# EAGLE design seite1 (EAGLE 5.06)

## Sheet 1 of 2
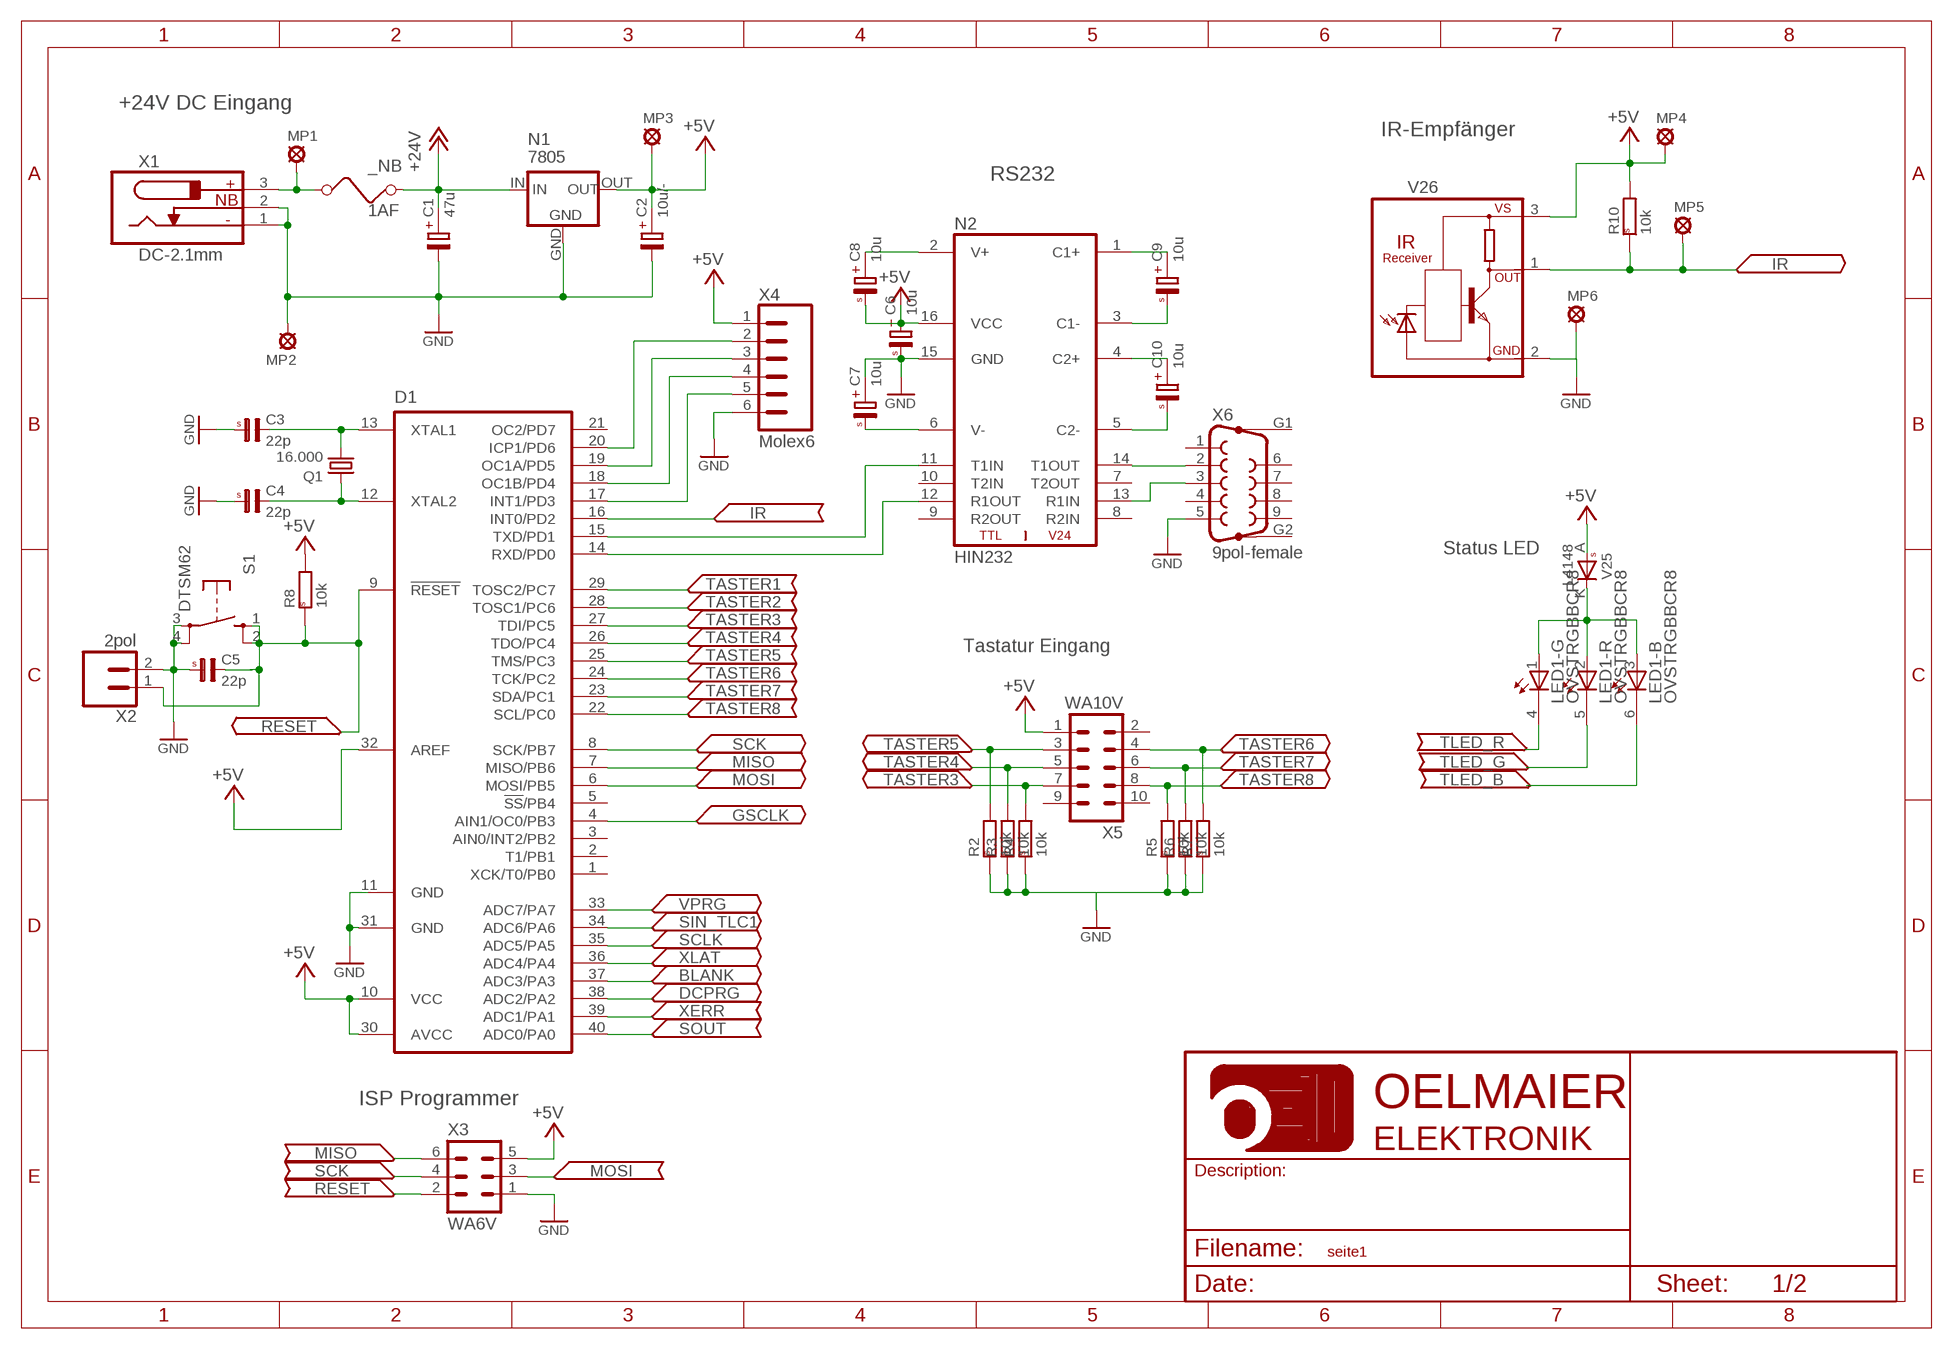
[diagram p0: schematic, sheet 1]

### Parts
_NB  1AF  FUSE5X20  [FUSE5X20]
C1  47u  E2,5-6  [E2,5-6]
C2  10u/-  E2,5-5  [E2,5-5]
C3  22p  C0805W  [C0805#W]
C4  22p  C0805W  [C0805#W]
C5  22p  C0805W  [C0805#W]
C6  10u  CE-B4  [CE-B4]
C7  10u  CE-B4  [CE-B4]
C8  10u  CE-B4  [CE-B4]
C9  10u  CE-B4  [CE-B4]
C10  10u  CE-B4  [CE-B4]
D1  ATMEGA16  [DIL40]
F1_H  FUSE_C1  [FUSE_C1]
LED1  OVSTRGBBCR8  [OVSTRGBBCR8]
MP1  LN13  [LN13]
MP2  LN13  [LN13]
MP3  LN13  [LN13]
MP4  LN13  [LN13]
MP5  LN13  [LN13]
MP6  LN13  [LN13]
N1  7805  78XXD2PAC  [D2PACVR]
N2  HIN232  MAX232-L  [SO16W#R]
Q1  16.000  Q_HC49P  [Q_HC49P]
R2  10k  R0603R1  [R06031#R]
R3  10k  R0603R1  [R06031#R]
R4  10k  R0603R1  [R06031#R]
R5  10k  R0603R1  [R06031#R]
R6  10k  R0603R1  [R06031#R]
R7  10k  R0603R1  [R06031#R]
R8  10k  R0603R1  [R06031#R]
R10  10k  R1206W1  [R12061#W]
S1  DTSM62  [DTSM62]
V25  L4148  DIODE-MLL34R  [MLL34#R]
V26  TSOP4836  [TSOP48]
X1  DC-2.1mm  DS-025B  [DS-025B]
X2  2pol  C254_02_SLV  [1X02]
X3  WA6V  WA06V  [WA06V]
X4  Molex6  C254_06_6410  [M6410_06]
X5  WA10V  [WA10V]
X6  9pol-female  F09HP  [F09HP]

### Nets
+5V: C2.+ C6.+ C8.- D1.10(VCC) D1.30(AVCC) D1.32(AREF) MP3.MP MP4.MP N1.OUT N2.16(VCC) R8.2 R10.2 V25.A V26.3(VS) X3.5 X4.1 X5.1 ; also sheet 2
+24V: C1.+ F1_H.2 F1_H.2A N1.IN ; also sheet 2
BLANK: D1.37(ADC3/PA3) ; also sheet 2
DCPRG: D1.38(ADC2/PA2) ; also sheet 2
F3: F1_H.1 F1_H.1A MP1.MP X1.3(+)
GND: C1.- C2.- C3.1 C4.1 C5.1 C6.- C7.+ D1.31(GND) MP2.MP MP6.MP N1.GND N2.15(GND) R2.1 R3.1 R4.1 R5.1 R6.1 R7.1 S1.3 S1.4 V26.2(GND) X1.1(-) X1.2(NB) X2.2 X3.1 X4.6 X6.5 ; also sheet 2
GSCLK: D1.4(AIN1/OC0/PB3) ; also sheet 2
IR: D1.16(INT0/PD2) MP5.MP R10.1 V26.1(OUT)
MISO: D1.7(MISO/PB6) X3.6
MOSI: D1.6(MOSI/PB5) X3.3
N$1: C3.2 D1.13(XTAL1) Q1.2
N$2: C4.2 D1.12(XTAL2) Q1.1
N$27: D1.20(ICP1/PD6) X4.2
N$28: D1.19(OC1A/PD5) X4.3
N$29: LED1.1(-G:A) LED1.3(-B:A) V25.K
N$30: D1.18(OC1B/PD4) X4.4
N$31: D1.17(INT1/PD3) X4.5
N$33: N2.14(T1OUT) X6.2
N$34: N2.13(R1IN) X6.3
N$35: C8.+ N2.2(V+)
N$38: C7.- N2.6(V-)
N$39: C9.+ N2.1(C1+)
N$40: C9.- N2.3(C1-)
N$41: C10.+ N2.4(C2+)
N$42: C10.- N2.5(C2-)
RESET: C5.2 D1.9(!RESET) R8.1 S1.1 S1.2 X2.1 X3.2
RXD: D1.14(RXD/PD0) N2.12(R1OUT)
SCK: D1.8(SCK/PB7) X3.4
SCLK: D1.35(ADC5/PA5) ; also sheet 2
SIN_TLC1: D1.34(ADC6/PA6) ; also sheet 2
SOUT: D1.40(ADC0/PA0) ; also sheet 2
TASTER1: D1.29(TOSC2/PC7)
TASTER2: D1.28(TOSC1/PC6)
TASTER3: D1.27(TDI/PC5) R4.2 X5.7
TASTER4: D1.26(TDO/PC4) R3.2 X5.5
TASTER5: D1.25(TMS/PC3) R2.2 X5.3
TASTER6: D1.24(TCK/PC2) R7.2 X5.4
TASTER7: D1.23(SDA/PC1) R6.2 X5.6
TASTER8: D1.22(SCL/PC0) R5.2 X5.8
TLED_B: LED1.6(-B:C) ; also sheet 2
TLED_G: LED1.5(-R:C) ; also sheet 2
TLED_R: LED1.4(-G:C) ; also sheet 2
TXD: D1.15(TXD/PD1) N2.11(T1IN)
VPRG: D1.33(ADC7/PA7) ; also sheet 2
XERR: D1.39(ADC1/PA1) ; also sheet 2
XLAT: D1.36(ADC4/PA4) ; also sheet 2
Unconnected: D1.1(XCK/T0/PB0) D1.2(T1/PB1) D1.3(AIN0/INT2/PB2) D1.5(!SS!/PB4) D1.11(GND) D1.21(OC2/PD7) LED1.2(-R:A) LED1.4@1(-G:C) LED1.5@1(-R:C) LED1.6@1(-B:C) N2.7(T2OUT) N2.8(R2IN) N2.9(R2OUT) N2.10(T2IN) X5.2 X5.9 X5.10 X6.1 X6.4 X6.6 X6.7 X6.8 X6.9 X6.G1 X6.G2

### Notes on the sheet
- +24V DC Eingang
- IR-Empfänger
- RS232
- Status LED
- Tastatur Eingang
- ISP Programmer

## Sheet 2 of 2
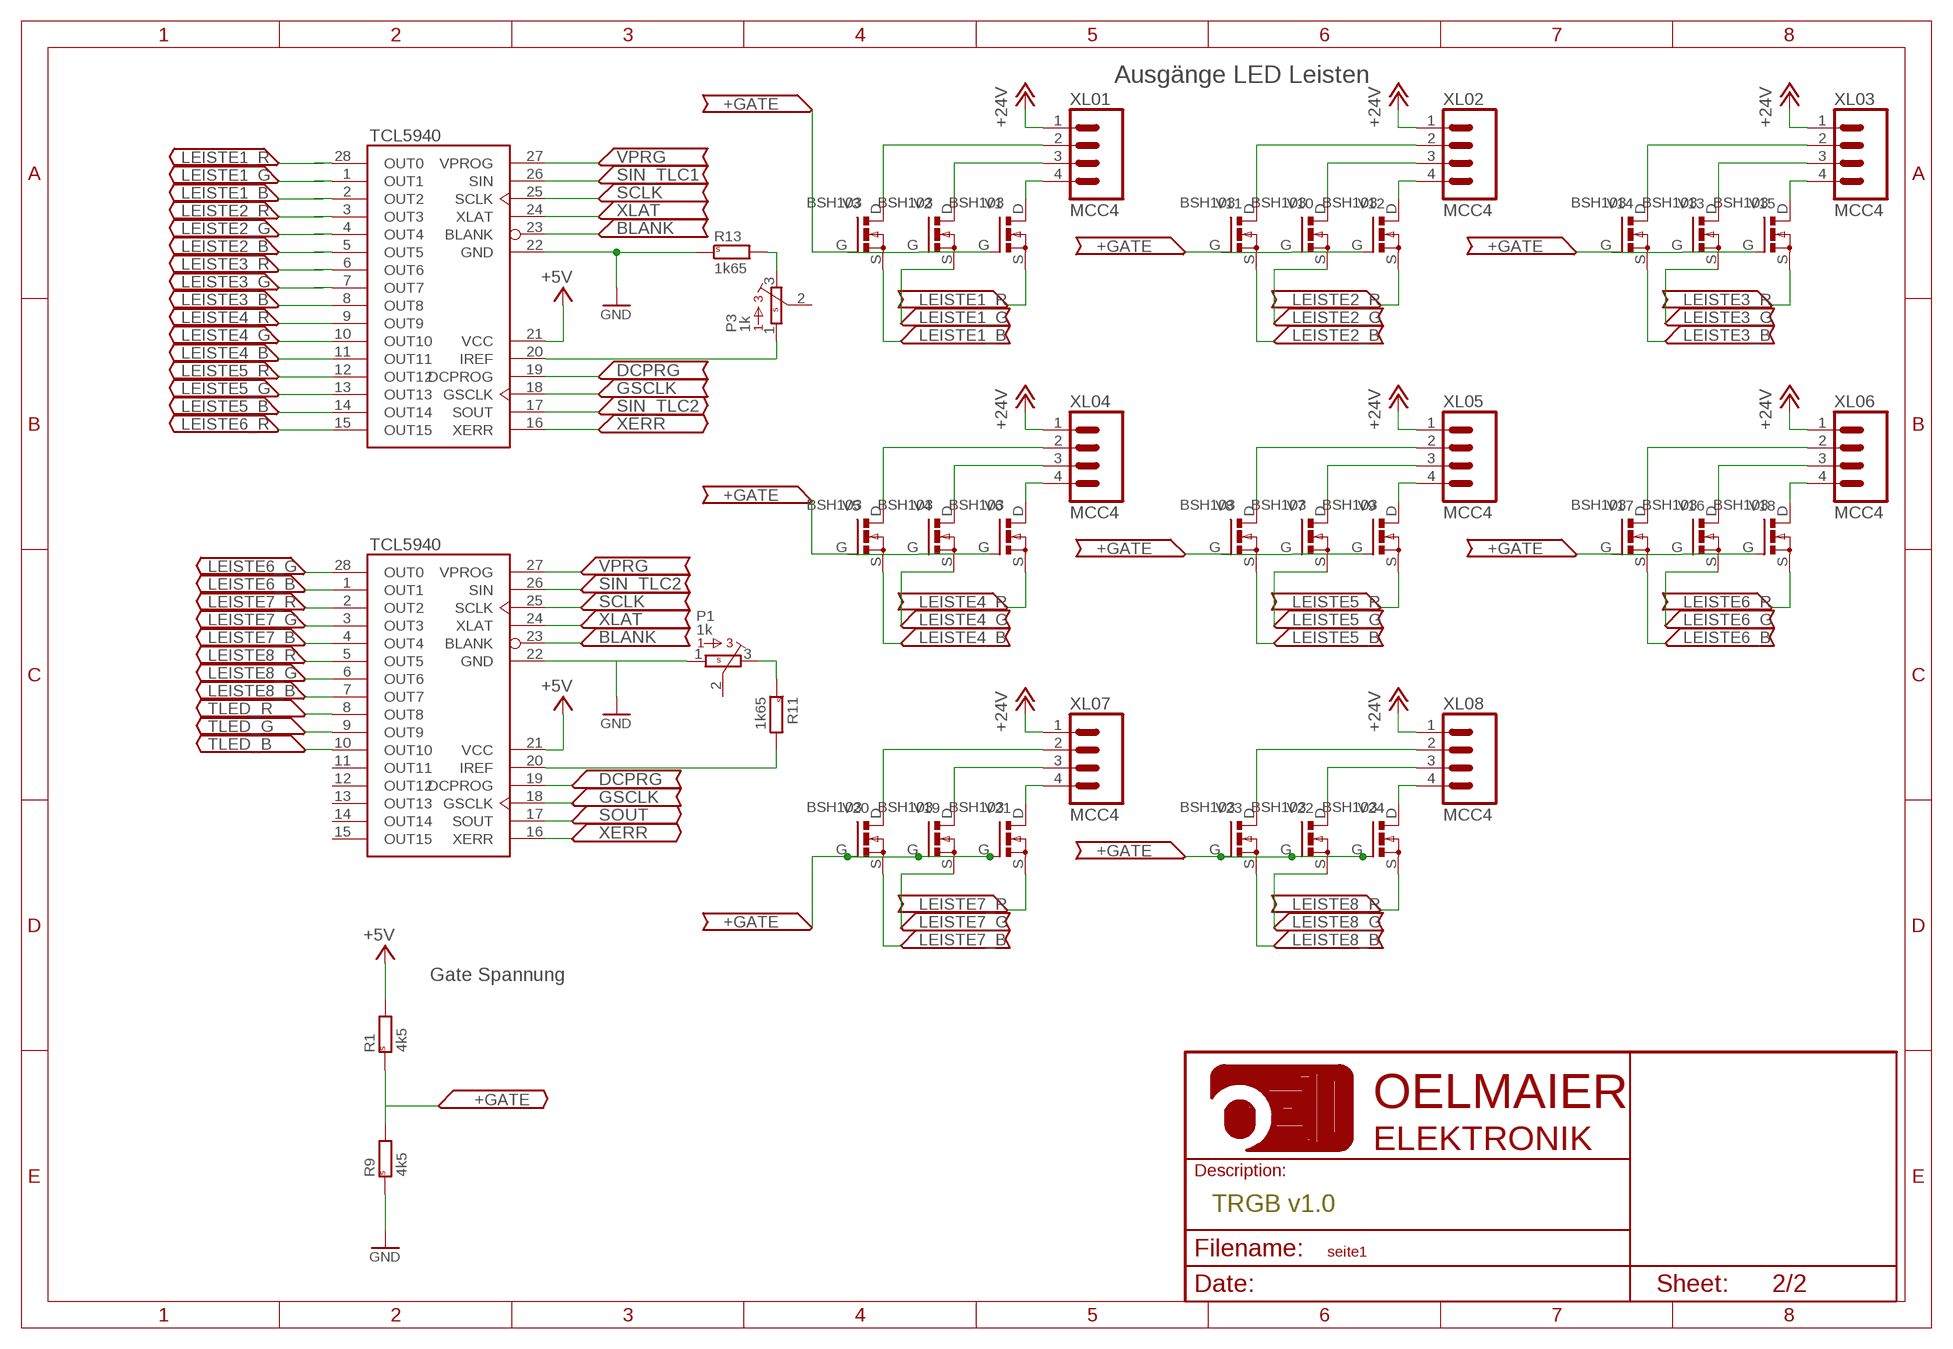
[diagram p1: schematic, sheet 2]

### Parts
IC1  TCL5940  [DIP28]
IC2  TCL5940  [DIP28]
P1  1k  TR-BI23B  [TR-BI23B]
P3  1k  TR-BI23B  [TR-BI23B]
R1  4k5  R1206W1  [R12061#W]
R9  4k5  R1206W1  [R12061#W]
R11  1k65  R1206W1  [R12061#W]
R13  1k65  R1206W1  [R12061#W]
V1  BSH103  MFET-SR  [SOT-23M#R]
V2  BSH103  MFET-SR  [SOT-23M#R]
V3  BSH103  MFET-SR  [SOT-23M#R]
V4  BSH103  MFET-SR  [SOT-23M#R]
V5  BSH103  MFET-SR  [SOT-23M#R]
V6  BSH103  MFET-SR  [SOT-23M#R]
V7  BSH103  MFET-SR  [SOT-23M#R]
V8  BSH103  MFET-SR  [SOT-23M#R]
V9  BSH103  MFET-SR  [SOT-23M#R]
V10  BSH103  MFET-SR  [SOT-23M#R]
V11  BSH103  MFET-SR  [SOT-23M#R]
V12  BSH103  MFET-SR  [SOT-23M#R]
V13  BSH103  MFET-SR  [SOT-23M#R]
V14  BSH103  MFET-SR  [SOT-23M#R]
V15  BSH103  MFET-SR  [SOT-23M#R]
V16  BSH103  MFET-SR  [SOT-23M#R]
V17  BSH103  MFET-SR  [SOT-23M#R]
V18  BSH103  MFET-SR  [SOT-23M#R]
V19  BSH103  MFET-SR  [SOT-23M#R]
V20  BSH103  MFET-SR  [SOT-23M#R]
V21  BSH103  MFET-SR  [SOT-23M#R]
V22  BSH103  MFET-SR  [SOT-23M#R]
V23  BSH103  MFET-SR  [SOT-23M#R]
V24  BSH103  MFET-SR  [SOT-23M#R]
XL01  MCC4  C381_04H  [AL381_04]
XL02  MCC4  C381_04H  [AL381_04]
XL03  MCC4  C381_04H  [AL381_04]
XL04  MCC4  C381_04H  [AL381_04]
XL05  MCC4  C381_04H  [AL381_04]
XL06  MCC4  C381_04H  [AL381_04]
XL07  MCC4  C381_04H  [AL381_04]
XL08  MCC4  C381_04H  [AL381_04]

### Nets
+5V: IC1.21(VCC) IC2.21(VCC) R1.2 ; also sheet 1
+24V: XL01.1 XL02.1 XL03.1 XL04.1 XL05.1 XL06.1 XL07.1 XL08.1 ; also sheet 1
+GATE: R1.1 R9.2 V1.G V2.G V3.G V4.G V5.G V6.G V7.G V8.G V9.G V10.G V11.G V12.G V13.G V14.G V15.G V16.G V17.G V18.G V19.G V20.G V21.G V22.G V23.G V24.G
BLANK: IC1.23(BLANK) IC2.23(BLANK) ; also sheet 1
DCPRG: IC1.19(DCPROG) IC2.19(DCPROG) ; also sheet 1
GND: IC1.22(GND) IC2.22(GND) P1.1 R9.1 R13.1 ; also sheet 1
GSCLK: IC1.18(GSCLK) IC2.18(GSCLK) ; also sheet 1
LEISTE1_B: IC1.2(OUT2) V3.S
LEISTE1_G: IC1.1(OUT1) V2.S
LEISTE1_R: IC1.28(OUT0) V1.S
LEISTE2_B: IC1.5(OUT5) V11.S
LEISTE2_G: IC1.4(OUT4) V10.S
LEISTE2_R: IC1.3(OUT3) V12.S
LEISTE3_B: IC1.8(OUT8) V14.S
LEISTE3_G: IC1.7(OUT7) V13.S
LEISTE3_R: IC1.6(OUT6) V15.S
LEISTE4_B: IC1.11(OUT11) V5.S
LEISTE4_G: IC1.10(OUT10) V4.S
LEISTE4_R: IC1.9(OUT9) V6.S
LEISTE5_B: IC1.14(OUT14) V8.S
LEISTE5_G: IC1.13(OUT13) V7.S
LEISTE5_R: IC1.12(OUT12) V9.S
LEISTE6_B: IC2.1(OUT1) V17.S
LEISTE6_G: IC2.28(OUT0) V16.S
LEISTE6_R: IC1.15(OUT15) V18.S
LEISTE7_B: IC2.4(OUT4) V20.S
LEISTE7_G: IC2.3(OUT3) V19.S
LEISTE7_R: IC2.2(OUT2) V21.S
LEISTE8_B: IC2.7(OUT7) V23.S
LEISTE8_G: IC2.6(OUT6) V22.S
LEISTE8_R: IC2.5(OUT5) V24.S
N$3: V1.D XL01.4
N$4: V2.D XL01.3
N$5: V3.D XL01.2
N$6: V12.D XL02.4
N$7: V10.D XL02.3
N$8: V11.D XL02.2
N$9: V15.D XL03.4
N$10: V13.D XL03.3
N$11: V14.D XL03.2
N$12: V6.D XL04.4
N$13: V4.D XL04.3
N$14: V5.D XL04.2
N$15: V9.D XL05.4
N$16: V7.D XL05.3
N$17: V8.D XL05.2
N$18: V18.D XL06.4
N$19: V16.D XL06.3
N$20: V17.D XL06.2
N$21: V21.D XL07.4
N$22: V19.D XL07.3
N$23: V20.D XL07.2
N$24: V24.D XL08.4
N$25: V22.D XL08.3
N$26: V23.D XL08.2
N$32: IC2.20(IREF) R11.2
N$36: P1.3 R11.1
N$37: IC1.20(IREF) P3.1
N$43: P3.3 R13.2
SCLK: IC1.25(SCLK) IC2.25(SCLK) ; also sheet 1
SIN_TLC1: IC1.26(SIN) ; also sheet 1
SIN_TLC2: IC1.17(SOUT) IC2.26(SIN)
SOUT: IC2.17(SOUT) ; also sheet 1
TLED_B: IC2.10(OUT10) ; also sheet 1
TLED_G: IC2.9(OUT9) ; also sheet 1
TLED_R: IC2.8(OUT8) ; also sheet 1
VPRG: IC1.27(VPROG) IC2.27(VPROG) ; also sheet 1
XERR: IC1.16(XERR) IC2.16(XERR) ; also sheet 1
XLAT: IC1.24(XLAT) IC2.24(XLAT) ; also sheet 1
Unconnected: IC2.11(OUT11) IC2.12(OUT12) IC2.13(OUT13) IC2.14(OUT14) IC2.15(OUT15) P1.2 P3.2

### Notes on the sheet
- Ausgänge LED Leisten
- Gate Spannung
- TRGB v1.0

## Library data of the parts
_NB = 6ICsocket:FUSE5X20: Feinsicherung 5 x 20mm
C1 C2 = 4CE:E2,5: Elko radial RM 2,5 mm
C3-C5 = 8SMDPAS:C: SMD Keramik Chip Kondensator
C6-C10 = 8SMDCE:CE-: SMD Chip Elko auf Kunststoffsockel
D1 = 2MCU:ATMEGA16: 8-bit AVR Microcontroller with 16K Bytes In-System Programmable Flash
F1_H = 6ICsocket:FUSE_C1: Sicherungsclipse 1Paar
IC1 IC2 = tcl5940:TCL5940: 16-Channel 12-Bit LED Driver
LED1 = led:OVSTRGBBCR8: Full Color PLCC6 LED OVSTRGBBCR8 Source: www.optekinc.com .. ovstrgbbcr8.pdf
MP1-MP6 = 6zCon-rib:LN13: Lötstützpunkt mit Öse (1.3mm Bohrung)
N1 = 7LINEAR:78XX: Festspannungsregler DPAK - D2PAK typ. 0.5 - 1A
N2 = 7LINEAR:MAX232-: RS232 TRANSEIVER
P1 P3 = 8SMDEMEC:TR-BI23B: SMD-Trimmer Beckmann BI23
Q1 = 8SMDPAS:Q_HC49P: SMD Quarz
R1-R11 R13 = 8SMDPAS:R: SMD Widerstand
S1 = 8SMDEMEC:DTSM62: SMD-Leiterplattentaster 6x6mm 1,6N Schaltspannung , max. : 12V DC Schaltstrom , max. : 50mA Lebensdauer : 1 Mio. Betätigungen Schaltart : schliesssend Betätigungskraft : 1,6N Betätigungsweg : 0,25mm
V1-V24 = 7SMDDIS:MFET-: N-Kanal MOSFET diverse Gehäuse
V25 = 7SMDDIS:DIODE-: Diode unipolar diverse Packages
V26 = 2OPTO:TSOP48*: IR Receiver Module for infrared remote control systems DeviceCarrier Frequency TSOP483030 kHz TSOP483333 kHz TSOP483636 kHz TSOP483736.7 kHz TSOP483838 kHz TSOP484040 kHz TSOP485656 kHz
X1 = 5CONSUBD:DS-025*: Klinkenbuchse DS-025-A : Mittelkontakt = 2.5 mm DS-025-AS : Mittelkontakt = 2.5 mm mit Schlitz DS-025-B : Mittelkontakt = 2.1 mm DS-025-BS : Mittelkontakt = 2.1 mm mit Schlitz
X2 = 5CON254H:C254_02: 2pol Stiftleiste einreihig RM2.54
X3 = 5CON254F:WA06: 6pol Wannenstiftleiste RM2.54
X4 = 5CON254H:C254_06: 6pol Stiftleiste einreihig RM2.54
X5 = 5CON254F:WA10: 10pol Wannenstiftleiste RM2.54
X6 = 5CONSUBD:F09HP
XL01-XL08 = 5CON381:C381_04: 4pol. Mini-Combicon RM3.81 Nenndaten : max. 160V / 8A Querschnitte max. : 1mm² flexibel / 1,5mm² starr

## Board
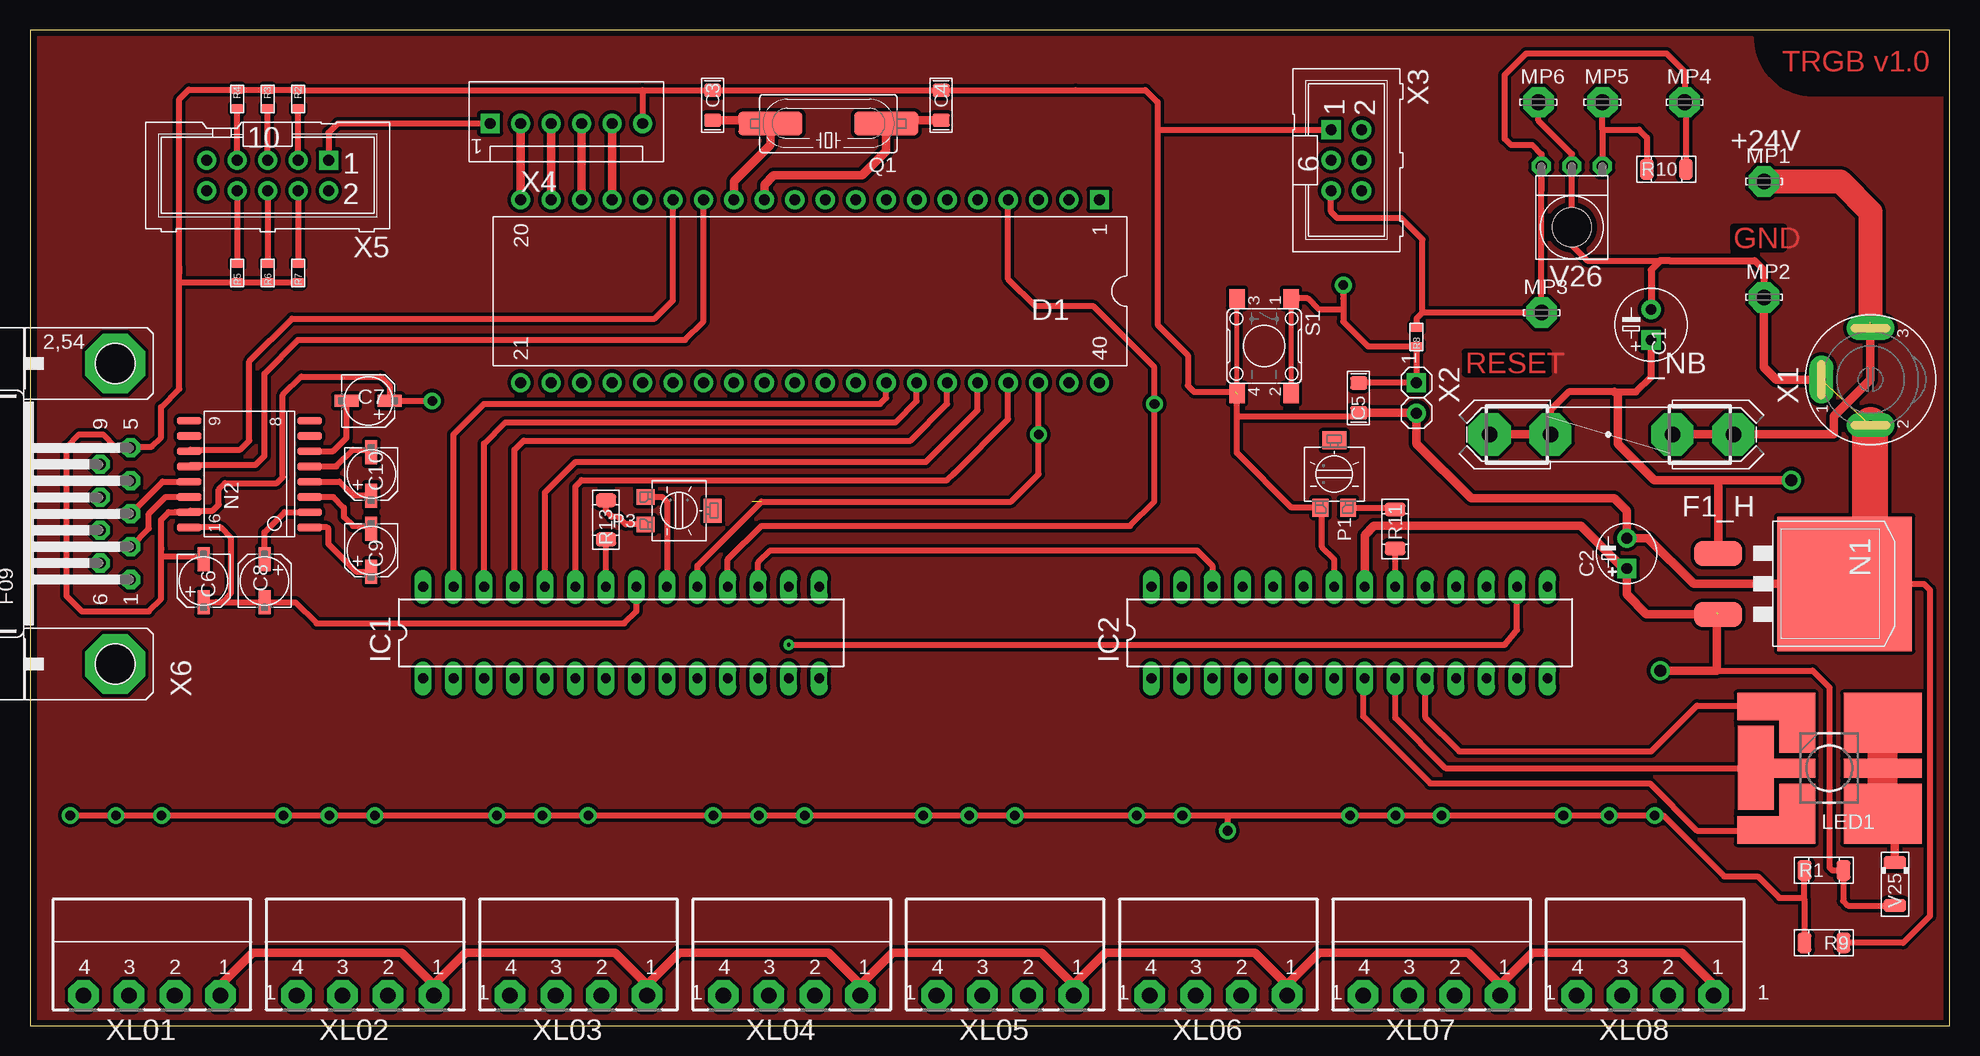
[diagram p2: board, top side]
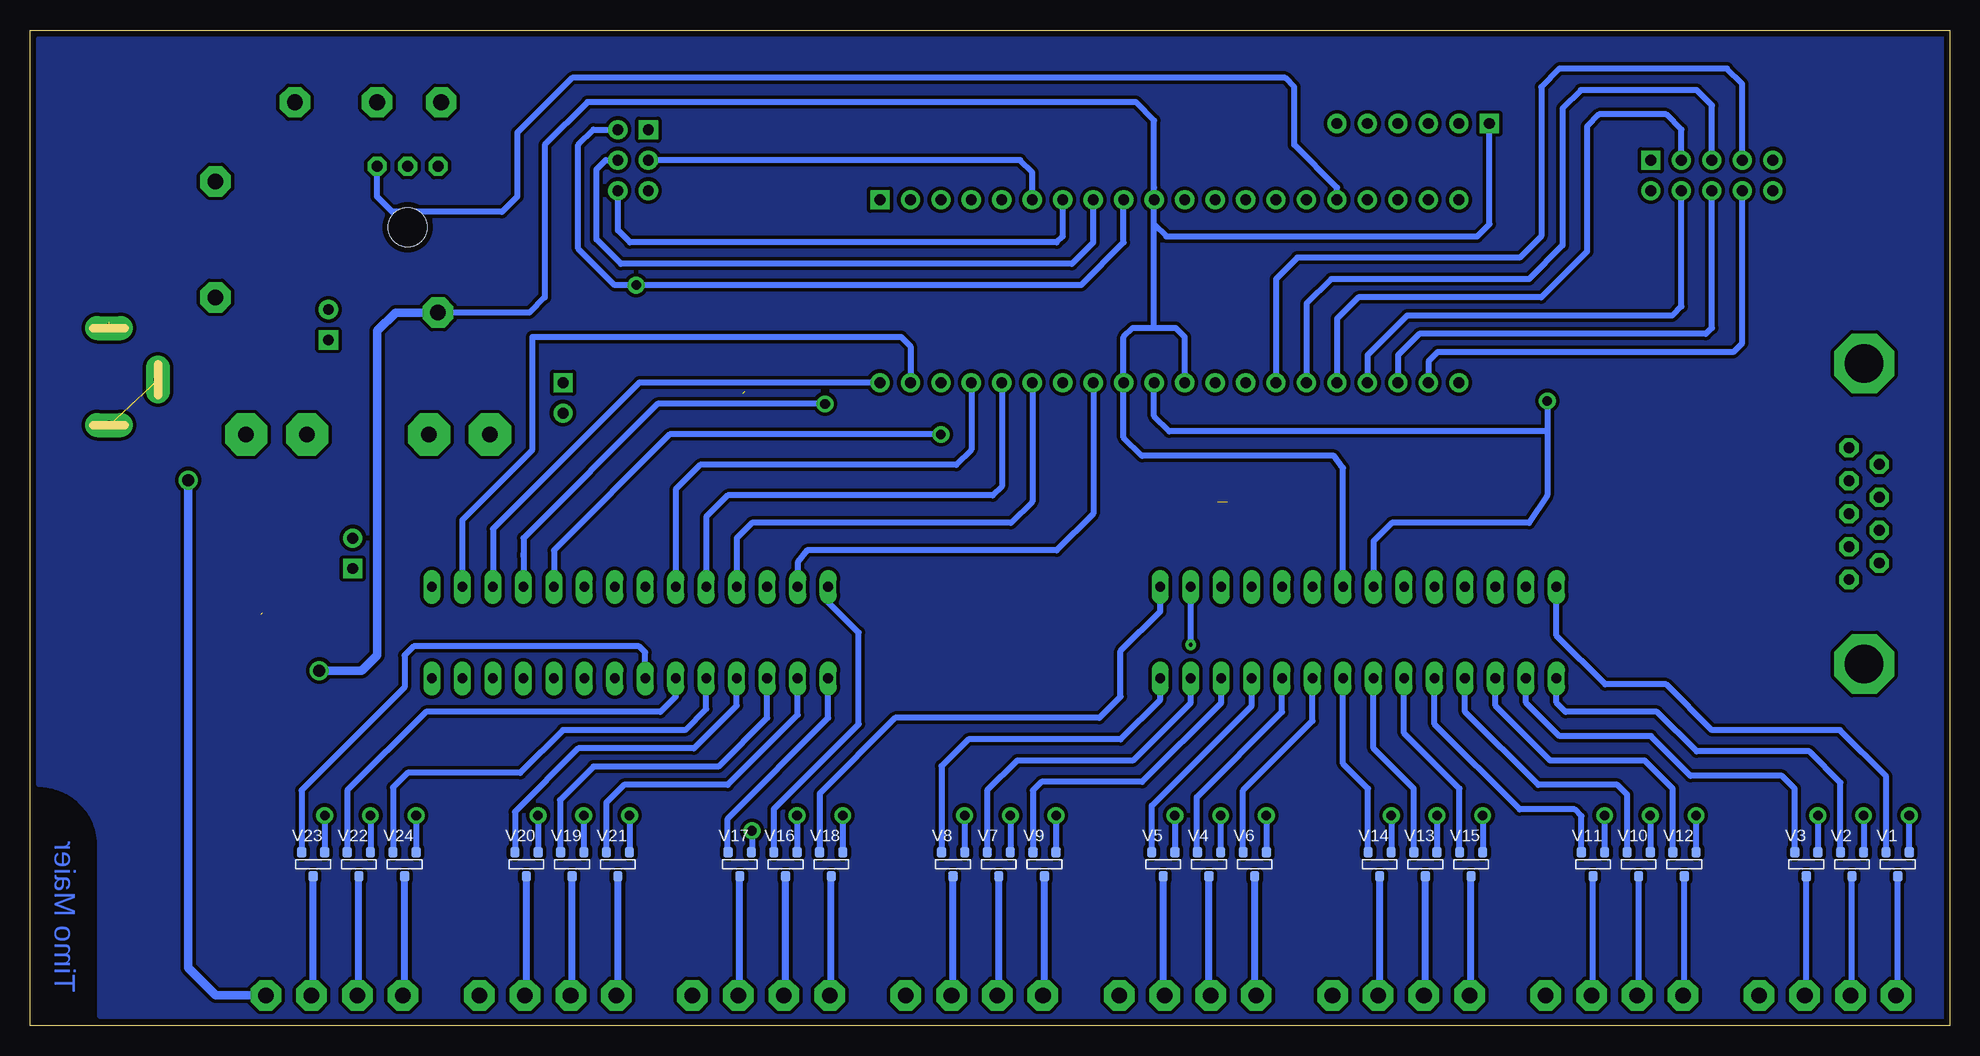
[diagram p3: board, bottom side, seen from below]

Size 160 x 82.98 mm. Coordinates in mm from the lower left corner, seen from the top.
Outline: 0,0 160,0 160,82.98 0,82.98 0,0
Copper layers (1*2*15*16): Top 0.07mm / dielectric 1.5mm / Route2 0.035mm / dielectric 1.5mm / Route15 0.035mm / dielectric 1.5mm / Bottom 0.07mm
Design rules "70um": minimum track width 0.3mm, minimum drill 0.3mm, track to track 0.3mm, track to pad 0.3mm, pad to pad 0.3mm, via to via 0.3mm, smd to smd 0.3mm, copper to edge 0.5mm, drill to drill 0.5mm, minimum pad ring 0.3mm, minimum via ring 0.3mm, stop-mask expansion 0mil, vias tented up to drill 0.6mm, thermal gap 0.3mm

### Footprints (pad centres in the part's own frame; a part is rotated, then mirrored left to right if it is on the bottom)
E2,5-6 = drill 0.9 pad 1.6 square: + -1.27,0 | drill 0.9 pad 1.6 round: - 1.27,0
E2,5-5 = drill 0.9 pad 1.6 square: + -1.27,0 | drill 0.9 pad 1.6 round: - 1.27,0
C0805#W = smd 1.092 x 1.397: 1 -1.245,0; 2 1.245,0
CE-B4 = smd 2 x 1: + -1.8,0; - 1.8,0
DIL40 = drill 0.9 pad 1.6 square: 1 -24.13,-7.62 | drill 0.9 pad 1.6 round: 2 -21.59,-7.62; 3 -19.05,-7.62; 4 -16.51,-7.62; 5 -13.97,-7.62; 6 -11.43,-7.62; 7 -8.89,-7.62; 8 -6.35,-7.62; 9 -3.81,-7.62; 10 -1.27,-7.62; 11 1.27,-7.62; 12 3.81,-7.62; 13 6.35,-7.62; 14 8.89,-7.62; 15 11.43,-7.62; 16 13.97,-7.62; 17 16.51,-7.62; 18 19.05,-7.62; 19 21.59,-7.62; 20 24.13,-7.62; 21 24.13,7.62; 22 21.59,7.62; 23 19.05,7.62; 24 16.51,7.62; 25 13.97,7.62; 26 11.43,7.62; 27 8.89,7.62; 28 6.35,7.62; 29 3.81,7.62; 30 1.27,7.62; 31 -1.27,7.62; 32 -3.81,7.62; 33 -6.35,7.62; 34 -8.89,7.62; 35 -11.43,7.62; 36 -13.97,7.62; 37 -16.51,7.62; 38 -19.05,7.62; 39 -21.59,7.62; 40 -24.13,7.62
FUSE_C1 = drill 1.3 pad 3.505 octagon: 1 -10.16,0; 1A -5.08,0; 2 10.16,0; 2A 5.08,0
DIP28 = drill 0.813 long: 1 -15.24,-3.81; 2 -12.7,-3.81; 3 -10.16,-3.81; 4 -7.62,-3.81; 5 -5.08,-3.81; 6 -2.54,-3.81; 7 0,-3.81; 8 2.54,-3.81; 9 5.08,-3.81; 10 7.62,-3.81; 11 10.16,-3.81; 12 12.7,-3.81; 13 15.24,-3.81; 14 17.78,-3.81; 15 17.78,3.81; 16 15.24,3.81; 17 12.7,3.81; 18 10.16,3.81; 19 7.62,3.81; 20 5.08,3.81; 21 2.54,3.81; 22 0,3.81; 23 -2.54,3.81; 24 -5.08,3.81; 25 -7.62,3.81; 26 -10.16,3.81; 27 -12.7,3.81; 28 -15.24,3.81
OVSTRGBBCR8 = smd 6.5 x 5: 1 -4.442,3.786; 3 -4.442,-3.786 | smd 6.5 x 1.6: 2 -4.442,0 | smd 3 x 5: 4 2.692,3.786; 6 2.692,-3.786 | smd 6.5 x 2.3: 4@1 4.442,5.136; 6@1 4.442,-5.136 | smd 5 x 1.6: 5 3.692,0 | smd 3 x 7: 5@1 6.15,-0.025
LN13 = drill 1.3 pad 2.54 octagon: MP 0,0
D2PACVR = smd 11.2 x 11.2: GND 0,3.175 | smd 2.08 x 4: IN -2.54,-7.366; OUT 2.54,-7.366
SO16W#R = smd 0.66 x 2.032: 1 -4.445,-5.029; 2 -3.175,-5.029; 3 -1.905,-5.029; 4 -0.635,-5.029; 5 0.635,-5.029; 6 1.905,-5.029; 7 3.175,-5.029; 8 4.445,-5.029; 9 4.445,5.029; 10 3.175,5.029; 11 1.905,5.029; 12 0.635,5.029; 13 -0.635,5.029; 14 -1.905,5.029; 15 -3.175,5.029; 16 -4.445,5.029
TR-BI23B = smd 1.5 x 1.3: 1 2.8,-1.15; 3 2.8,1.15 | smd 1.5 x 2: 2 -2.8,0
Q_HC49P = smd 5.334 x 1.93: 1 -4.826,0; 2 4.826,0
R12061#W = smd 1.143 x 1.702: 1 -1.626,0; 2 1.626,0
R06031#R = smd 0.762 x 0.965: 1 -0.787,0; 2 0.787,0
DTSM62 = smd 1.55 x 1.3: 1 -3.975,2.25; 2 3.975,2.25; 3 -3.975,-2.25; 4 3.975,-2.25
SOT-23M#R = smd 0.787 x 0.889: D 0,-1.016; G 0.965,1.016; S -0.965,1.016
MLL34#R = smd 1.1 x 1.9: A -1.8,0; K 1.8,0
TSOP48 = drill 0.9 pad 1.6 octagon: 1 -2.54,-5.08; 2 0,-5.08; 3 2.54,-5.08 | hole 3.2: 0,0
DS-025B = drill 0.711 pad 2 long: 1 0,4.1; 2 -3.8,0; 3 4.3,0
1X02 = drill 0.9 pad 1.6 square: 1 -1.27,0 | drill 0.9 pad 1.6 round: 2 1.27,0
WA06V = drill 0.9 pad 1.6 square: 1 -2.54,-1.27 | drill 0.9 pad 1.6 round: 2 -2.54,1.27; 3 0,-1.27; 4 0,1.27; 5 2.54,-1.27; 6 2.54,1.27
M6410_06 = drill 0.9 pad 1.6 square: 1 -6.35,0 | drill 0.9 pad 1.6 round: 2 -3.81,0; 3 -1.27,0; 4 1.27,0; 5 3.81,0; 6 6.35,0
WA10V = drill 0.9 pad 1.6 square: 1 -5.08,-1.27 | drill 0.9 pad 1.6 round: 2 -5.08,1.27; 3 -2.54,-1.27; 4 -2.54,1.27; 5 0,-1.27; 6 0,1.27; 7 2.54,-1.27; 8 2.54,1.27; 9 5.08,-1.27; 10 5.08,1.27
F09HP = drill 0.9 pad 1.6 octagon: 1 -5.486,-1.27; 2 -2.743,-1.27; 3 0,-1.27; 4 2.743,-1.27; 5 5.486,-1.27; 6 -4.115,1.27; 7 -1.372,1.27; 8 1.372,1.27; 9 4.115,1.27 | drill 3.2 pad 4.978 octagon: G1 -12.522,0; G2 12.522,0
AL381_04 = drill 1.3 pad 2.54 octagon: 1 5.715,0; 2 1.905,0; 3 -1.905,0; 4 -5.715,0

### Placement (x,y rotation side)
_NB  131.57,49.28 0 top
C1  135.13,58.42 90 top
C2  133.1,39.37 90 top
C3  56.9,76.71 270 top
C4  75.95,76.71 270 top
C5  110.74,52.32 90 top
C6  14.48,37.08 90 top
C7  28.19,52.07 180 top
C8  19.56,37.08 270 top
C9  28.45,39.62 90 top
C10  28.45,45.97 90 top
D1  65.02,61.21 180 top
F1_H  131.83,49.28 180 top
IC1  48.01,32.77 0 top
IC2  108.71,32.77 0 top
LED1  149.99,21.46 180 top
MP1  144.53,70.36 0 top
MP2  144.53,60.71 0 top
MP3  125.98,59.44 0 top
MP4  137.92,76.96 0 top
MP5  131.06,76.96 0 top
MP6  125.73,76.96 0 top
N1  148.08,36.83 270 top
N2  18.29,45.97 90 top
P1  108.71,45.97 270 top
P3  54.1,42.93 180 top
Q1  66.55,75.18 180 top
R1  149.53,12.95 0 top
R2  22.35,77.22 270 top
R3  19.81,77.22 270 top
R4  17.27,77.22 270 top
R5  17.27,62.74 90 top
R6  19.81,62.74 90 top
R7  22.35,62.74 90 top
R8  115.57,57.4 90 top
R9  149.53,6.91 180 top
R10  136.4,71.37 0 top
R11  113.79,41.4 270 top
R13  48.01,42.16 90 top
S1  102.87,56.64 270 top
V1  4.32,13.46 0 bottom
V2  8.13,13.46 0 bottom
V3  11.94,13.46 0 bottom
V4  61.72,13.46 0 bottom
V5  65.53,13.46 0 bottom
V6  57.91,13.46 0 bottom
V7  79.25,13.46 0 bottom
V8  83.06,13.46 0 bottom
V9  75.44,13.46 0 bottom
V10  25.91,13.46 0 bottom
V11  29.72,13.46 0 bottom
V12  22.1,13.46 0 bottom
V13  43.69,13.46 0 bottom
V14  47.5,13.46 0 bottom
V15  39.88,13.46 0 bottom
V16  97.03,13.46 0 bottom
V17  100.84,13.46 0 bottom
V18  93.22,13.46 0 bottom
V19  114.81,13.46 0 bottom
V20  118.62,13.46 0 bottom
V21  111,13.46 0 bottom
V22  132.59,13.46 0 bottom
V23  136.4,13.46 0 bottom
V24  128.78,13.46 0 bottom
V25  155.45,11.81 90 top
V26  128.52,66.55 180 top
X1  153.42,53.85 90 top
X2  115.57,52.32 270 top
X3  109.73,72.14 270 top
X4  44.7,75.18 0 top
X5  19.81,70.87 180 top
X6  7.11,42.67 90 top
XL01  10.16,2.54 0 top
XL02  27.94,2.54 0 top
XL03  45.72,2.54 0 top
XL04  63.5,2.54 0 top
XL05  81.28,2.54 0 top
XL06  99.06,2.54 0 top
XL07  116.84,2.54 0 top
XL08  134.62,2.54 0 top

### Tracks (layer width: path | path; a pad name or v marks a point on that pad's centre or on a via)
+5V  (via drill 1 pad 1.5)  (1 unrouted)
  Top 0.5: C6.+ 14.5,35.31 15.49,35.31 | 15.49,35.31 16,35.31 16.76,36.07 16.76,40.64 15.88,41.53 N2.16 | 15.49,35.31 19.54,35.31 C8.- 22.12,35.28 23.88,33.53 49.53,33.53 50.55,34.54 IC1.21 | R8.2 115.57,58.93 116.08,59.44 | 116.08,59.44 MP3.MP 125.98,70.61 | 116.08,59.44 116.08,65.53 114.3,67.31 108.97,67.31 108.46,67.82 X3.5 | 125.98,70.61 125.98,69.6 | R10.2 138.02,76.86 MP4.MP 137.92,79.5 136.4,81.03 124.71,81.03 122.94,79.25 122.94,73.91 123.44,73.41 125.22,73.41 125.98,72.64 V26.3 125.98,70.61 | 140.08,29.59 148.59,29.59 149.99,28.19 149.99,13.21 150.24,12.95 R1.2 151.13,12.93 151.13,10.41 151.53,10.01 V25.A | X5.1 24.89,74.42 25.65,75.18 X4.1
  Top 0.7: 131.57,39.37 132.84,38.1 C2.+ 133.1,35.94 134.75,34.29 N1.OUT | 131.57,39.37 131.06,39.88 | 140.59,34.42 140.59,29.59 140.08,29.59 v135.89,29.59 | 131.57,39.37 129.29,41.66 112.01,41.66 111.25,40.89 IC2.21
  Bottom 0.5: 66.29,69.34 D1.10 66.29,66.8 | 66.29,69.34 66.29,69.85 | 66.29,58.17 68.07,58.17 68.83,57.4 D1.32 68.83,49.02 67.31,47.5 51.31,47.5 50.55,46.48 IC1.21 | 66.29,58.17 64.52,58.17 63.75,57.4 D1.30 | 66.29,58.17 66.29,66.8 | 66.29,69.34 66.29,75.44 67.82,76.96 113.54,76.96 117.09,73.41 117.09,60.71 118.36,59.44 MP3.MP | 66.29,66.8 65.28,65.79 39.37,65.79 38.35,66.8 X4.1
  Bottom 0.7: v135.89,29.59 132.33,29.59 131.06,30.86 131.06,57.91 129.54,59.44 MP3.MP
+24V  (via drill 1 pad 1.5)
  Top 0.6: F1_H.2A 126.75,51.31 128.27,52.83 132.08,52.83 133.86,52.83 135.13,54.1 C1.+
  Top 0.7: F1_H.2A F1_H.2 | 132.08,52.83 132.33,52.58 132.33,48.51 135.38,45.47 140.72,45.47 | XL08.1 140.34,3.43 137.67,6.1 125.22,6.1 122.68,3.56 122.68,2.67 XL07.1 122.56,3.43 119.89,6.1 107.44,6.1 104.9,3.56 104.9,2.67 XL06.1 104.78,3.43 102.11,6.1 89.66,6.1 87.12,3.56 87.12,2.67 XL05.1 87,3.43 84.33,6.1 71.88,6.1 69.34,3.56 69.34,2.67 XL04.1 69.22,3.43 66.55,6.1 54.1,6.1 51.56,3.56 51.56,2.67 XL03.1 51.44,3.43 48.77,6.1 36.32,6.1 33.78,3.56 33.78,2.67 XL02.1 33.66,3.43 30.99,6.1 18.54,6.1 16,3.56 16,2.67 XL01.1 | 140.72,45.47 N1.IN | v146.81,45.47 140.72,45.47
  Bottom 0.7: v146.81,45.47 146.81,4.83 144.53,2.54 XL08.1
+GATE  (via drill 0.8 pad 1.2)
  Top 0.5: v3.35,17.53 v7.16,17.53 v10.97,17.53 v21.13,17.53 v24.94,17.53 v28.75,17.53 v38.91,17.53 v42.72,17.53 v46.53,17.53 v56.95,17.53 v60.76,17.53 v64.57,17.53 v74.47,17.53 v78.28,17.53 v82.09,17.53 v92.25,17.53 v96.06,17.53 99.82,17.53 | 99.82,17.53 v110.03,17.53 v113.84,17.53 v117.65,17.53 v127.81,17.53 v131.62,17.53 v135.43,17.53 136.14,17.53 141.22,12.45 144.02,12.45 145.8,10.67 147.78,10.67 147.9,10.54 | 99.82,17.53 v99.82,16.26 | 147.9,10.54 R9.2 | 147.9,10.54 R1.1
  Bottom 0.5: v127.81,17.53 V24.G | v131.62,17.53 V22.G | v135.43,17.53 V23.G | v92.25,17.53 V18.G | v96.06,17.53 V16.G | v110.03,17.53 V21.G | v113.84,17.53 V19.G | v117.65,17.53 V20.G | V1.G v3.35,17.53 | v7.16,17.53 V2.G | v10.97,17.53 V3.G | v21.13,17.53 V12.G | v24.94,17.53 V10.G | v28.75,17.53 V11.G | v38.91,17.53 V15.G | v42.72,17.53 V13.G | v46.53,17.53 V14.G | v56.95,17.53 V6.G | v60.76,17.53 V4.G | v64.57,17.53 V5.G | v74.47,17.53 V9.G | v78.28,17.53 V7.G | v82.09,17.53 V8.G | v99.82,16.26 99.82,14.53 V17.G
ASD
  pour Top (isolate 0.3, no thermals): 0.76,82.3 0.76,45.97 0.76,9.65 0.76,0.51 159.51,0.51 159.51,3.3 159.51,77.22 156.46,77.22 148.59,77.22 arc-90 143.51,82.3
ASDF
  pour Bottom (isolate 0.3, no thermals): 0.51,82.3 0.51,0.76 2.79,0.76 154.18,0.76 154.18,3.05 154.18,14.99 arc-90 159.26,20.07 159.26,82.3
BLANK
  Top 0.5: 77.09,46.1 76.96,45.97 | 77.09,46.1 81.53,50.55 D1.37 | 77.09,46.1 76.45,45.47 45.97,45.47 45.47,44.96 IC1.23
  Bottom 0.5: D1.37 81.53,48.01 82.8,46.74 104.14,46.74 106.17,44.7 IC2.23
DCPRG  (via drill 0.8 pad 1.2)  (1 unrouted)
  Top 0.5: D1.38 v84.07,49.28 84.07,45.97 81.79,43.69 60.96,43.69 55.63,38.35 IC1.19
  Bottom 0.5: IC2.19 116.33,39.62 106.68,49.28 v84.07,49.28
F3  (1 unrouted)
  Top 0.7: 142.49,49.28 F1_H.1 | 142.49,49.28 150.37,49.28 150.37,50.8 153.42,53.85 X1.3 | F1_H.1A 142.49,49.28
  Top 2: MP1.MP 150.88,70.36 153.42,67.82 153.42,58.67
GND  (via drill 0.8 pad 1.2)  (2 unrouted)
  Top 0.4: S1.4 S1.3
  Top 0.5: C6.- 14.46,38.86 14.2,39.12 10.92,39.12 | 10.92,39.88 10.92,39.62 | 10.92,39.88 10.92,42.16 11.56,42.8 N2.15 | N2.15 12.06,42.8 | 8.48,48.26 10.16,48.26 10.92,49.02 10.92,51.56 12.45,53.09 12.45,61.98 | 8.48,48.26 X6.5 | N2.15 13.39,42.93 15.24,42.93 15.75,43.43 15.75,44.7 16.26,45.21 20.57,45.21 21.08,45.72 21.08,52.58 22.61,54.1 29.21,54.1 29.99,53.32 C7.+ v33.53,52.07 | 12.45,63.25 12.45,62.74 | 12.45,63.25 12.45,77.22 13.23,78 R4.1 R3.1 R2.1 22.38,77.98 51.05,77.98 | R7.1 R6.1 R5.1 12.47,61.95 12.45,61.98 | 8.48,48.26 7.11,48.26 6.1,49.28 4.06,49.28 3.05,48.26 3.05,35.81 4.32,34.54 9.91,34.54 10.92,35.56 10.92,39.12 | 10.92,39.12 10.92,39.88 | MP6.MP 125.73,75.44 128.52,72.64 V26.2 128.52,65.02 129.79,63.75 136.65,63.75 | 93.98,74.68 93.98,76.96 92.96,77.98 87.17,77.98 87.15,77.95 C4.1 C3.1 56.87,77.98 51.05,77.98 | 93.98,74.68 93.98,58.42 96.52,55.88 96.52,53.34 97.03,52.83 100.45,52.83 | 93.98,74.68 X3.1 | N1.GND 157.86,36.83 158.37,36.32 158.37,9.14 156.13,6.91 R9.1 | C5.1 110.47,50.8 100.58,50.8 | 115.55,51.08 X2.2 | 51.05,77.98 X4.6 | IC1.22 R13.1 | 100.58,50.8 100.58,47.75 105.16,43.17 P1.1 107.7,43.04 107.7,39.88 108.71,38.86 IC2.22 | 100.58,50.8 100.58,52.63 S1.4 | 12.45,61.98 12.45,63.25
  Top 0.6: MP2.MP 144.53,62.99 143.76,63.75 136.65,63.75 135.89,63.75 135.13,62.99 C1.-
  Top 0.7: X1.1 145.54,53.85 144.53,54.86 MP2.MP | X2.2 115.57,48.51 120.14,43.94 132.08,43.94 133.1,42.93 C2.- 134.87,40.64 138.68,36.83 N1.GND | C5.1 115.55,51.08
  Top 3: X1.2 153.42,34.16 N1.GND
  Bottom 0.5: v33.53,52.07 33.53,49.53 | 33.53,49.53 33.53,44.2 35.05,41.91 46.48,41.91 48.01,40.39 IC1.22 | D1.31 66.29,50.8 65.02,49.53 33.53,49.53
GSCLK  (via drill 0.8 pad 1.2)
  Top 0.5: D1.4 81.53,62.23 83.82,59.94 88.65,59.94 93.73,54.86 v93.73,51.82 93.73,43.69 91.69,41.66 60.96,41.66 58.17,38.86 IC1.18
  Bottom 0.5: 118.87,39.12 IC2.18 | 118.87,39.12 118.87,39.37 | v93.73,51.82 107.7,51.82 118.87,40.64 118.87,39.12
IR
  Top 0.5: 131.06,74.68 MP5.MP | R10.1 134.77,74.02 134.11,74.68 131.06,74.68 | 131.06,74.68 V26.1
  Bottom 0.5: D1.16 51.05,69.85 54.61,73.41 54.61,78.23 55.37,78.99 114.81,78.99 119.38,74.42 119.38,69.09 120.65,67.82 129.79,67.82 131.06,69.09 V26.1
LEISTE1_B
  Bottom 0.5: V3.S 12.9,19.76 13.97,20.83 21.59,20.83 24.89,24.13 32.51,24.13 35.31,26.92 IC1.2
LEISTE1_G
  Bottom 0.5: V2.S 9.09,20.27 11.68,22.86 21.08,22.86 24.38,26.16 32,26.16 32.77,26.92 IC1.1
LEISTE1_R
  Bottom 0.5: V1.S 5.28,20.78 9.14,24.64 19.81,24.64 23.62,28.45 28.7,28.45 32.77,32.51 IC1.28
LEISTE2_B
  Bottom 0.5: V11.S 30.68,17.48 31.24,18.03 35.81,18.03 42.93,25.15 IC1.5
LEISTE2_G
  Bottom 0.5: V10.S 26.87,19.25 27.69,20.07 34.29,20.07 40.39,26.16 IC1.4
LEISTE2_R
  Bottom 0.5: V12.S 23.06,19.76 25.4,22.1 33.27,22.1 37.85,26.67 IC1.3
LEISTE3_B
  Bottom 0.5: V14.S 48.46,19.76 50.55,21.84 IC1.8
LEISTE3_G
  Bottom 0.5: V13.S 44.65,19.76 48.01,23.11 IC1.7
LEISTE3_R
  Bottom 0.5: V15.S 40.84,19.76 45.47,24.38 IC1.6
LEISTE4_B
  Bottom 0.5: IC1.11 58.17,26.67 66.5,18.34 V5.S
LEISTE4_G
  Bottom 0.5: IC1.10 55.63,26.16 62.74,19.05 62.74,14.53 V4.S
LEISTE4_R
  Bottom 0.5: V6.S 58.88,19.61 53.09,25.4 IC1.9
LEISTE5_B
  Bottom 0.5: IC1.14 65.79,27.18 69.09,23.88 81.79,23.88 84.02,21.64 V8.S
LEISTE5_G
  Bottom 0.5: V7.S 80.21,19.61 77.72,22.1 68.07,22.1 63.25,26.92 IC1.13
LEISTE5_R
  Bottom 0.5: V9.S 76.4,19.61 75.69,20.32 67.31,20.32 60.71,26.92 IC1.12
LEISTE6_B
  Bottom 0.5: IC2.1 93.47,25.65 101.85,17.27 101.85,14.53 V17.S
LEISTE6_G
  Bottom 0.5: IC2.28 93.47,35.31 90.93,32.77 90.93,25.15 97.99,18.09 V16.S
LEISTE6_R
  Bottom 0.5: V18.S 94.18,19.36 87.88,25.65 70.87,25.65 69.09,27.43 69.09,31.24 65.79,34.54 IC1.15
LEISTE7_B
  Bottom 0.5: V20.S 119.58,17.83 114.3,23.11 104.65,23.11 101.09,26.67 IC2.4
LEISTE7_G
  Bottom 0.5: V19.S 115.82,14.53 115.82,18.8 113.03,21.59 102.62,21.59 98.55,25.65 IC2.3
LEISTE7_R
  Bottom 0.5: V21.S 111.96,18.59 110.49,20.07 101.85,20.07 96.01,25.91 IC2.2
LEISTE8_B
  Bottom 0.5: V23.S 137.36,19.61 128.78,28.19 128.78,30.86 128.02,31.62 109.22,31.62 108.71,31.11 IC2.7
LEISTE8_G
  Bottom 0.5: V22.S 133.55,19.61 127,26.16 107.44,26.16 106.17,27.43 IC2.6
LEISTE8_R
  Bottom 0.5: IC2.5 103.63,26.42 105.41,24.64 115.57,24.64 119.13,21.08 128.52,21.08 129.74,19.86 V24.S
MISO
  Bottom 0.5: D1.7 73.91,65.79 74.42,65.28 109.98,65.28 111,66.29 X3.6
MOSI
  Bottom 0.5: X3.3 77.47,72.14 76.45,71.12 D1.6
N$1
  Top 0.7: D1.13 58.67,70.36 61.72,73.41 Q1.2 61.44,75.46 C3.2
N$2
  Top 0.7: D1.12 61.21,70.1 61.98,70.87 69.34,70.87 71.37,72.9 Q1.1 71.65,75.46 C4.2
N$3
  Bottom 0.5: 4.32,2.67 V1.D
  Bottom 0.6: XL01.4 4.32,2.67
N$4
  Bottom 0.5: 8.13,2.67 V2.D
  Bottom 0.6: XL01.3 8.13,2.67
N$5
  Bottom 0.5: 11.94,2.67 V3.D
  Bottom 0.6: XL01.2 11.94,2.67
N$6
  Bottom 0.5: 22.1,2.67 V12.D
  Bottom 0.6: XL02.4 22.1,2.67
N$7
  Bottom 0.5: 25.91,2.67 V10.D
  Bottom 0.6: XL02.3 25.91,2.67
N$8
  Bottom 0.5: 29.72,2.67 V11.D
  Bottom 0.6: XL02.2 29.72,2.67
N$9
  Bottom 0.6: V15.D 39.88,2.67 XL03.4
N$10
  Bottom 0.6: V13.D 43.69,2.67 XL03.3
N$11
  Bottom 0.6: V14.D 47.5,2.67 XL03.2
N$12
  Bottom 0.6: V6.D 57.91,2.67 XL04.4
N$13
  Bottom 0.6: V4.D 61.72,2.67 XL04.3
N$14
  Bottom 0.6: V5.D 65.53,2.67 XL04.2
N$15
  Bottom 0.6: V9.D 75.44,2.67 XL05.4
N$16
  Bottom 0.6: V7.D 79.25,2.67 XL05.3
N$17
  Bottom 0.6: V8.D 83.06,2.67 XL05.2
N$18
  Bottom 0.6: V18.D 93.22,2.67 XL06.4
N$19
  Bottom 0.6: V16.D 97.03,2.67 XL06.3
N$20
  Bottom 0.6: V17.D 100.84,2.67 XL06.2
N$21
  Bottom 0.6: V21.D 111,2.67 XL07.4
N$22
  Bottom 0.6: V19.D 114.81,2.67 XL07.3
N$23
  Bottom 0.6: V20.D 118.62,2.67 XL07.2
N$24
  Bottom 0.6: V24.D 128.78,2.67 XL08.4
N$25
  Bottom 0.6: V22.D 132.59,2.67 XL08.3
N$26
  Bottom 0.6: V23.D 136.4,2.67 XL08.2
N$27
  Top 0.7: D1.20 X4.2
N$28
  Top 0.7: D1.19 X4.3
N$29
  Top 0.7: V25.K 155.45,16.66 LED1.1
  Top 2.5: LED1.1 LED1.3
N$30
  Top 0.7: D1.18 X4.4
N$31
  Top 0.7: D1.17 X4.5
N$32
  Top 0.5: IC2.20 R11.2
N$33
  Top 0.5: X6.2 9.91,41.45 9.91,42.67 11.3,44.07 N2.14
N$34
  Top 0.5: X6.3 11.05,45.34 N2.13
N$35
  Top 0.5: C8.+ 19.56,41.15 21.21,42.8 N2.2
N$36
  Top 0.5: P1.3 113.79,43.17 R11.1
N$37
  Top 0.5: P3.1 52.7,44.08 53.09,43.69 IC1.20
N$38
  Top 0.5: 26.16,51.84 C7.- 26.39,49 25.27,47.88 N2.6
N$39
  Top 0.5: C9.+ 28.43,37.85 27.18,37.85 24.89,40.13 24.89,41.4 24.77,41.53 N2.1
N$40
  Top 0.5: C9.- 28.22,41.66 26.92,41.66 26.16,42.42 26.16,43.18 25.27,44.07 N2.3
N$41
  Top 0.5: C10.+ 28.43,44.2 26.92,44.2 25.78,45.34 N2.4
N$42
  Top 0.5: C10.- 28.45,47.75 28.19,48.01 26.92,48.01 25.53,46.61 N2.5
N$43
  Top 0.5: P3.3 49.66,41.78 49.02,42.42 48.51,42.42 48.01,42.93 R13.2
RESET  (via drill 0.8 pad 1.2)
  Top 0.4: S1.1 S1.2
  Top 0.5: S1.2 105.23,52.55 | v109.47,61.72 109.47,60.96 | 109.47,60.96 109.47,59.69 | 109.47,59.69 109.47,58.67 111.53,56.62 R8.1 X2.1 115.55,53.57 C5.2 | 109.47,60.96 109.47,60.62 | S1.1 106.52,60.62 107.44,59.69 109.47,59.69
  Bottom 0.5: D1.9 68.83,65.28 72.39,61.72 v109.47,61.72 111.25,61.72 114.3,64.77 114.3,73.41 113.03,74.68 X3.2
RXD
  Top 0.5: D1.14 56.13,58.67 54.61,57.15 22.35,57.15 19.56,54.36 19.56,47.5 18.8,46.74 13.39,46.74 N2.12
SCK
  Bottom 0.5: D1.8 71.37,65.28 73.15,63.5 110.74,63.5 112.78,65.53 112.78,71.37 112.01,72.14 X3.4
SCLK
  Top 0.5: D1.35 76.45,51.82 73.41,48.77 41.15,48.77 40.39,48.01 IC1.25
  Bottom 0.5: D1.35 76.45,43.69 78.23,41.91 99.82,41.91 101.09,40.64 IC2.25
SIN_TLC1
  Top 0.5: D1.34 73.91,52.07 72.14,50.29 39.62,50.29 37.85,48.51 IC1.26
SIN_TLC2
  Top 0.5: IC1.17 60.71,38.61 61.72,39.62 97.28,39.62 98.55,38.35 IC2.26
SOUT
  Bottom 0.5: IC2.17 121.41,41.4 109.22,53.59 D1.40
TASTER3
  Top 0.5: X5.7 R4.2
  Bottom 0.5: X5.7 17.27,78.49 18.54,79.76 32.51,79.76 34.04,78.23 34.04,65.79 35.81,64.01 54.36,64.01 56.13,62.23 D1.27
TASTER4
  Top 0.5: X5.5 R3.2
  Bottom 0.5: X5.5 19.81,76.71 21.08,77.98 30.73,77.98 32.26,76.45 32.26,65.02 35.05,62.23 51.56,62.23 53.59,60.2 D1.26
TASTER5
  Top 0.5: X5.3 R2.2
  Bottom 0.5: X5.3 22.35,74.68 23.62,75.95 29.21,75.95 30.23,74.93 30.23,64.52 34.04,60.71 49.28,60.71 51.05,58.93 D1.25
TASTER6
  Top 0.5: X5.4 R7.2
  Bottom 0.5: D1.24 48.51,55.88 45.21,59.18 23.11,59.18 22.35,59.94 X5.4
TASTER7
  Top 0.5: X5.6 R6.2
  Bottom 0.5: D1.23 45.97,55.88 44.2,57.66 20.32,57.66 19.81,58.17 X5.6
TASTER8
  Top 0.5: X5.8 R5.2
  Bottom 0.5: D1.22 43.43,55.37 42.67,56.13 18.03,56.13 17.27,56.9 X5.8
TLED_B
  Top 0.5: LED1.6 147.29,26.42 146.05,26.42 146.05,26.67 138.94,26.67 135.13,22.86 119.13,22.86 116.33,25.65 IC2.10
TLED_G
  Top 0.5: LED1.5 117.98,21.46 113.79,25.65 IC2.9
TLED_R
  Top 0.5: LED1.4 147.29,16.26 138.94,16.26 135,20.19 116.71,20.19 111.12,25.78 111.12,28.83 IC2.8
TXD
  Top 0.5: D1.15 53.59,60.45 52.07,58.93 21.84,58.93 18.29,55.37 18.29,48.77 17.53,48.01 13.39,48.01 N2.11
VPRG
  Top 0.5: D1.33 71.37,52.32 70.87,51.82 37.85,51.82 35.31,49.28 IC1.27
  Bottom 0.5: IC2.27 96.01,38.61 95.25,39.62 74.42,39.62 71.37,42.67 D1.33
XERR  (via drill 0.3 pad 0.9)
  Top 0.5: 123.8,32.83 122.94,31.75 v63.25,31.75 | 123.8,32.83 123.95,33.02 | IC2.16 123.95,32.98 123.8,32.83
  Bottom 0.5: v63.25,31.75 IC1.16 | D1.39 86.61,56.64 87.38,57.4 118.11,57.4 118.11,48.01 123.95,42.16 IC2.16
XLAT
  Top 0.5: 75.56,47.88 75.18,47.5 | 75.56,47.88 78.99,51.31 D1.36 | IC1.24 42.93,44.45 45.47,46.99 74.68,46.99 75.56,47.88
  Bottom 0.5: D1.36 78.99,44.96 79.76,44.2 101.85,44.2 103.63,42.42 IC2.24

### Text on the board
Top: TRGB v1.0 | GND | RESET
Bottom: Timo Maier
tNames: +24V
